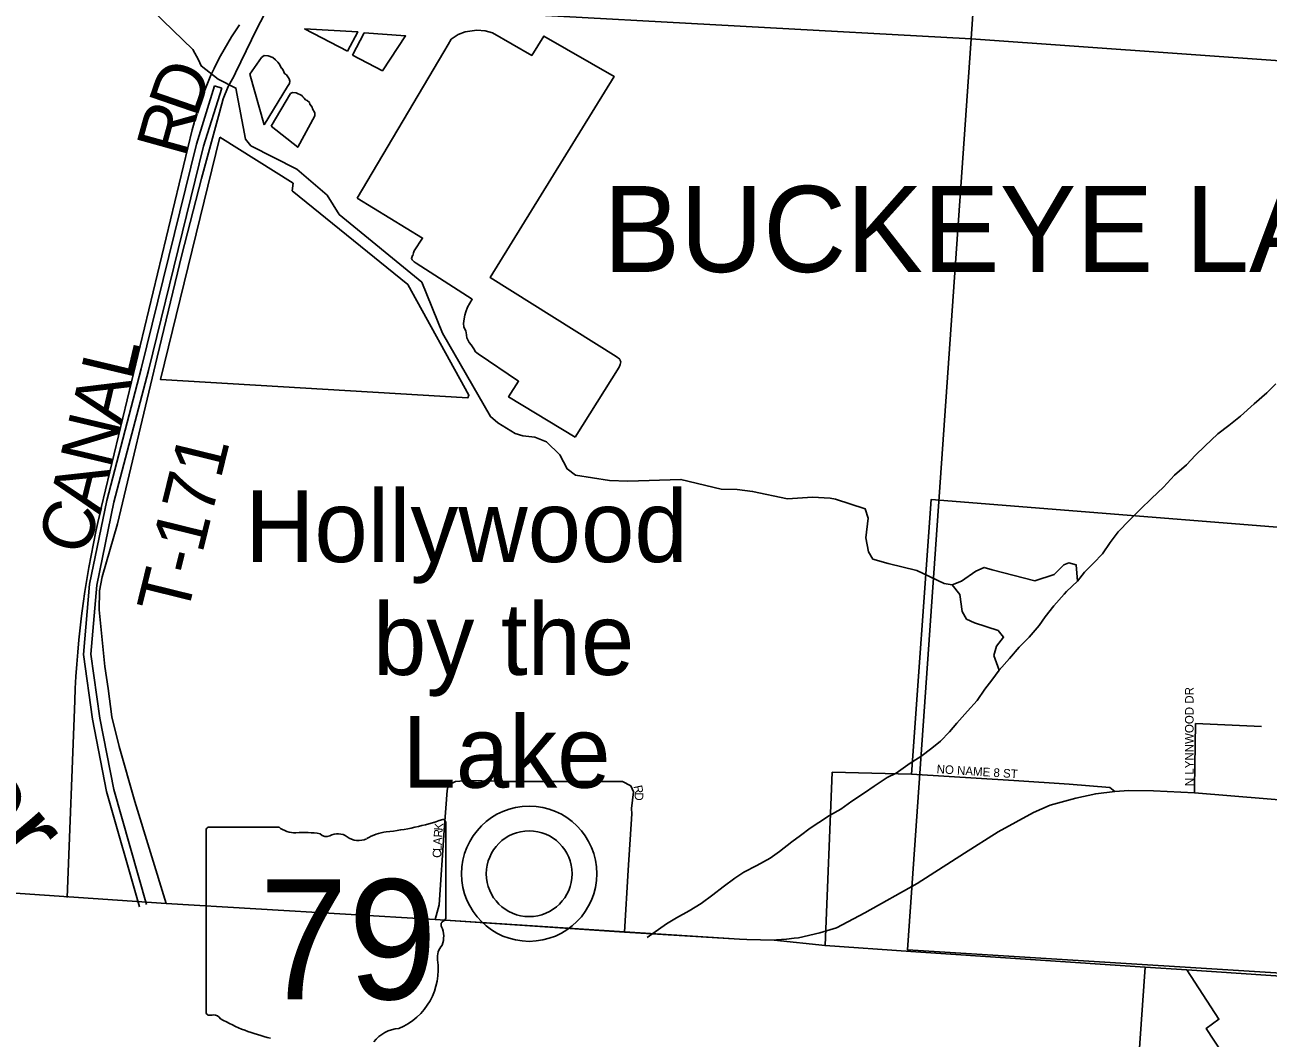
# Model space of a CAD drawing. Extents: x 0 to 40.4, y 0 to 22.
# Drawn here: x 4.97 to 6.339, y 14.615 to 15.73 of the extents above; entities that cross this region are included whole.
import ezdxf

# ---------------------------------------------------------------- set-up
doc = ezdxf.new("R2010")
doc.units = 0
for name, color, linetype in [('GM_X_Adjacent_County_Text', 7, 'Continuous'), ('GM_X_City_Street', 7, 'Continuous'), ('GM_X_City_Street_Text', 7, 'Continuous'), ('GM_X_Corporation', 7, 'Continuous'), ('GM_X_Corporation_Text', 7, 'Continuous'), ('GM_X_County', 7, 'Continuous'), ('GM_X_Major_River', 7, 'Continuous'), ('GM_X_Major_River_Text', 7, 'Continuous'), ('GM_X_Minor_Lake', 7, 'Continuous'), ('GM_X_Minor_River', 7, 'Continuous'), ('GM_X_Section', 7, 'Continuous'), ('GM_X_State_Route', 7, 'Continuous'), ('GM_X_State_Shield', 7, 'Continuous'), ('GM_X_Township_Road', 7, 'Continuous'), ('GM_X_Township_Road_Text', 7, 'Continuous'), ('GM_X_Township_Subdivision', 7, 'Continuous'), ('GM_X_Township_Subdivision_Text', 7, 'Continuous'), ('GM_X_Unincorporated', 7, 'Continuous'), ('GM_X_Unincorporated_Text', 7, 'Continuous'), ('SH_Data', 7, 'Continuous')]:
    doc.layers.add(name, color=color, linetype=linetype)

msp = doc.modelspace()

# ---------------------------------------------------------------- linework, layer by layer
at = {"layer": 'GM_X_City_Street'}
for points in [[(6.2578, 14.8849), (6.2579, 14.8912), (6.259, 14.961)], [(6.259, 14.961), (6.3317, 14.9578)], [(5.9465, 14.9054), (6.0591, 14.8982)], [(6.0591, 14.8982), (6.1198, 14.8943), (6.1646, 14.8906), (6.1702, 14.8863)]]:
    msp.add_lwpolyline(points, dxfattribs=at)
at = {"layer": 'GM_X_Corporation'}
for points in [[(6.1961, 14.5886), (6.2034, 14.693), (5.9456, 14.7103), (5.8513, 14.7168), (5.8591, 14.9075), (5.9465, 14.9054), (5.9681, 15.2076), (6.5188, 15.1635), (6.5553, 15.6693), (6.5616, 15.9075)], [(6.369, 14.682), (6.2494, 14.69), (6.2847, 14.6357), (6.2708, 14.6255), (6.2966, 14.5858)]]:
    msp.add_lwpolyline(points, dxfattribs=at)
at = {"layer": 'GM_X_County'}
msp.add_lwpolyline([(2.6, 14.9098), (3.7816, 14.849), (3.7947, 14.8444), (4.3781, 14.8049), (4.5187, 14.7962), (4.7718, 14.7855), (4.9113, 14.7777), (5.1259, 14.7632), (5.4221, 14.7453), (5.6303, 14.7317), (5.757, 14.7237), (5.765, 14.7235), (5.7951, 14.7228), (5.8513, 14.7168), (5.9456, 14.7103), (6.2034, 14.693), (6.2494, 14.69), (6.369, 14.682), (6.4224, 14.6785), (7.5441, 14.6124), (8.0846, 14.9692), (9.4, 14.8681)], dxfattribs=at)
at = {"layer": 'GM_X_Major_River'}
for points in [[(6.1144, 15.1035), (6.117, 15.1063), (6.1292, 15.1176), (6.1368, 15.1274), (6.1466, 15.1373), (6.1565, 15.1478), (6.1649, 15.1603), (6.174, 15.1721), (6.1865, 15.1849), (6.1983, 15.197), (6.2104, 15.2087), (6.2237, 15.2212), (6.2359, 15.2344), (6.2492, 15.2457), (6.259, 15.2563), (6.2693, 15.2661), (6.2837, 15.2797), (6.2955, 15.2888), (6.3084, 15.2993), (6.3236, 15.3126), (6.3376, 15.325), (6.3475, 15.3348)], [(5.6554, 14.7255), (5.6766, 14.7406), (5.6876, 14.7474), (5.7016, 14.755), (5.7149, 14.763), (5.7278, 14.7724), (5.7392, 14.7812), (5.7517, 14.791), (5.7619, 14.7975), (5.776, 14.8047), (5.7908, 14.813), (5.801, 14.8202), (5.8147, 14.8308), (5.8241, 14.8377), (5.8348, 14.846), (5.8443, 14.8521), (5.856, 14.86), (5.8685, 14.8668), (5.8807, 14.8756), (5.8947, 14.8847), (5.9053, 14.8923), (5.9194, 14.9017), (5.9296, 14.9063), (5.9448, 14.9173), (5.9565, 14.9249), (5.9687, 14.934), (5.9782, 14.9415), (5.988, 14.9518), (5.9964, 14.9616), (6.0081, 14.9745), (6.0188, 14.9863), (6.0271, 14.9988), (6.0347, 15.0087), (6.043, 15.0197), (6.0544, 15.0326), (6.065, 15.0451), (6.076, 15.0561), (6.0867, 15.069), (6.0935, 15.0785), (6.103, 15.0906), (6.1144, 15.1035)]]:
    msp.add_lwpolyline(points, dxfattribs=at)
at = {"layer": 'GM_X_Minor_Lake'}
for points in [[(5.278, 15.7255), (5.3254, 15.7007)], [(5.3254, 15.7007), (5.3368, 15.7222), (5.278, 15.7255)], [(5.3311, 15.6965), (5.364, 15.6793), (5.3895, 15.7175), (5.3438, 15.7211)], [(5.3438, 15.7211), (5.3311, 15.6965)], [(5.5762, 15.276), (5.6247, 15.3532), (5.6258, 15.3562), (5.6262, 15.3589), (5.6258, 15.3604), (5.6251, 15.3619), (5.6213, 15.365), (5.4827, 15.4516), (5.6189, 15.673), (5.5417, 15.7173), (5.5283, 15.6961), (5.4852, 15.7209), (5.4772, 15.7233), (5.4677, 15.724), (5.4552, 15.7222), (5.4472, 15.7192), (5.4396, 15.7139), (5.4362, 15.7082), (5.4316, 15.6999), (5.3362, 15.539)], [(5.2309, 15.6938), (5.2179, 15.6756), (5.2337, 15.6198)], [(5.2337, 15.6198), (5.2596, 15.6618), (5.2615, 15.6652), (5.2619, 15.6679), (5.2612, 15.6702), (5.2585, 15.6747), (5.2563, 15.6762), (5.2547, 15.68), (5.2532, 15.6819), (5.2529, 15.6819), (5.2502, 15.6869), (5.2487, 15.6888), (5.2461, 15.6911), (5.2434, 15.6937), (5.2381, 15.6957), (5.2336, 15.6961), (5.2309, 15.6938)], [(5.0965, 14.7595), (5.0601, 14.8864), (5.0448, 14.9657), (5.0348, 15.037), (5.0415, 15.1144), (5.0604, 15.2065), (5.0985, 15.3513), (5.1593, 15.5984), (5.1792, 15.6625)], [(5.1043, 14.7618), (5.0681, 14.8883), (5.0529, 14.967), (5.0431, 15.0373), (5.0496, 15.1132), (5.0684, 15.2047), (5.1064, 15.3493), (5.1671, 15.5962), (5.187, 15.6601)], [(5.1792, 15.6625), (5.187, 15.6601)], [(5.2895, 15.6298), (5.2895, 15.6329), (5.2868, 15.6374), (5.2865, 15.6393), (5.2842, 15.6424), (5.2835, 15.6443), (5.2812, 15.6466), (5.2793, 15.6473), (5.2778, 15.6492), (5.2763, 15.6504), (5.2751, 15.6519), (5.2691, 15.655), (5.2687, 15.655), (5.2649, 15.6554), (5.2626, 15.6542), (5.2416, 15.6183)], [(5.2416, 15.6183), (5.2708, 15.595), (5.2895, 15.6298)], [(5.1851, 15.6063), (5.1197, 15.3395), (5.458, 15.3194), (5.4591, 15.3223), (5.392, 15.444), (5.2645, 15.5472), (5.2657, 15.5556)], [(5.2657, 15.5556), (5.1851, 15.6063)], [(5.3362, 15.539), (5.4081, 15.4951), (5.399, 15.4811), (5.3982, 15.4788), (5.3975, 15.4758), (5.3971, 15.4758), (5.3959, 15.4728), (5.3967, 15.4713), (5.3986, 15.4694), (5.3989, 15.469), (5.4012, 15.4674), (5.4629, 15.4278), (5.4576, 15.4191), (5.4557, 15.4141), (5.4545, 15.4103), (5.4541, 15.4062), (5.4533, 15.4012), (5.4537, 15.3974), (5.4556, 15.3929), (5.456, 15.3914), (5.4567, 15.3853), (5.4593, 15.3804), (5.4616, 15.3777), (5.4646, 15.3731), (5.4665, 15.3701), (5.4695, 15.3678), (5.5138, 15.3377), (5.5028, 15.3203), (5.5762, 15.276)]]:
    msp.add_lwpolyline(points, dxfattribs=at)
at = {"layer": 'GM_X_Minor_River'}
for points in [[(6.1292, 15.1176), (6.1277, 15.1355), (6.1197, 15.1378), (6.114, 15.1356), (6.1034, 15.125), (6.0821, 15.1182), (6.0351, 15.1302), (6.0264, 15.1328), (6.0173, 15.1287), (6.0013, 15.1178), (5.9911, 15.1136), (5.9823, 15.1152), (5.9524, 15.1293), (5.9206, 15.137), (5.9039, 15.142), (5.899, 15.15), (5.896, 15.1652), (5.8987, 15.1868), (5.8954, 15.1971), (5.8628, 15.2078), (5.8567, 15.209), (5.8374, 15.2102), (5.8097, 15.2084), (5.7714, 15.2165), (5.7543, 15.2184), (5.7369, 15.2189), (5.6925, 15.2297), (5.6341, 15.2276), (5.614, 15.2284), (5.5765, 15.2343), (5.5674, 15.2411), (5.5591, 15.2567), (5.5447, 15.2708), (5.5318, 15.2761), (5.5186, 15.2777), (5.5102, 15.28), (5.4909, 15.2918), (5.483, 15.2987), (5.4302, 15.3907), (5.4072, 15.4466), (5.3164, 15.5212), (5.3032, 15.5422), (5.2699, 15.5711), (5.2192, 15.5967), (5.2131, 15.6039), (5.2027, 15.6601), (5.183, 15.6701), (5.1645, 15.6845), (5.1615, 15.6914), (5.1551, 15.7028), (4.969, 15.8829)], [(6.043, 15.0197), (6.0371, 15.0357), (6.0398, 15.0463), (6.0478, 15.0561), (6.0417, 15.0634), (6.0156, 15.0718), (6.0069, 15.076), (6.002, 15.0844), (5.9997, 15.103), (5.9911, 15.1136)]]:
    msp.add_lwpolyline(points, dxfattribs=at)
at = {"layer": 'GM_X_Section'}
for points in [[(6.0805, 16.728), (6.012, 15.7142), (5.5033, 15.7422), (5.57, 16.7542)], [(6.0805, 16.728), (6.3929, 16.7053), (6.6625, 16.6858), (6.5945, 15.6728), (6.012, 15.7142)], [(6.012, 15.7142), (6.5945, 15.6728), (6.5001, 14.6771), (5.9421, 14.7119)]]:
    msp.add_lwpolyline(points, close=True, dxfattribs=at)
at = {"layer": 'GM_X_State_Route'}
for points in [[(5.8173, 14.7248), (5.822, 14.7253), (5.8456, 14.7308), (5.8638, 14.7362), (5.895, 14.7527), (5.9526, 14.7852), (6.0047, 14.8184), (6.0416, 14.8418), (6.0806, 14.8632), (6.099, 14.8711), (6.1272, 14.8789), (6.1491, 14.8838), (6.1702, 14.8863), (6.1857, 14.8875), (6.2126, 14.8871), (6.2578, 14.8849), (6.3777, 14.875), (6.4338, 14.8704), (6.4868, 14.8662)], [(3.7816, 14.849), (3.7947, 14.8444), (4.3781, 14.8049), (4.5187, 14.7962), (4.7718, 14.7855), (4.9113, 14.7777), (5.1259, 14.7632)], [(5.1259, 14.7632), (5.4221, 14.7453), (5.6303, 14.7316), (5.757, 14.7237), (5.765, 14.7235), (5.7951, 14.7228), (5.7977, 14.723)], [(5.7977, 14.723), (5.8087, 14.7239), (5.8173, 14.7248)]]:
    msp.add_lwpolyline(points, dxfattribs=at)
at = {"layer": 'GM_X_State_Shield'}
for p, q in [((5.4336, 14.7474), (5.4336, 14.8521)), ((5.17, 14.8437), (5.17, 14.6436)), ((5.2498, 14.8471), (5.1726, 14.8471)), ((5.4336, 14.7474), (5.4336, 14.7474))]:
    msp.add_line(p, q, dxfattribs=at)
for centre, radius, start, end in [((5.3397, 15.12), 0.2796, 275.8445, 288.9065), ((5.4307, 14.8525), 0.00294, 351.8621, 97.738), ((5.173, 14.8441), 0.00305, 98.1301, 188.1301), ((5.2682, 14.8704), 0.0296, 231.6195, 271.1119), ((5.278, 14.7348), 0.1064, 80.4867, 94.9883), ((5.3021, 14.8451), 0.00855, 219.7921, 297.1024), ((5.3147, 14.822), 0.0178, 54.4667, 119.1411), ((5.3376, 14.8537), 0.0214, 233.8562, 294.8282), ((5.3754, 14.786), 0.0563, 97.3462, 120.7689), ((5.433, 14.7397), 0.00454, 107.944, 210.337), ((5.4305, 14.747), 0.00314, 289.6038, 7.7341), ((5.4041, 14.7265), 0.0273, 340.033, 23.6496), ((5.4442, 14.7036), 0.0198, 136.8065, 186.9296), ((5.3554, 14.6903), 0.0699, 292.3089, 8.9858), ((5.173, 14.6431), 0.00308, 171.9584, 258.3066), ((5.1735, 14.6636), 0.0235, 267.339, 280.6039), ((5.1783, 14.632), 0.00848, 29.7484, 93.2717), ((5.2854, 14.8118), 0.2019, 240.4129, 257.1985), ((5.3849, 14.5874), 0.0383, 94.4031, 142.5768)]:
    msp.add_arc(centre, radius, start, end, dxfattribs=at)
at = {"layer": 'GM_X_Township_Road'}
for points in [[(5.2022, 15.6769), (5.2257, 15.7255), (5.2467, 15.7656), (5.2646, 15.7968), (5.2981, 15.843), (5.3281, 15.8846), (5.3786, 15.9538), (5.3927, 15.9705), (5.4131, 15.9925), (5.4141, 15.9936)], [(5.1259, 14.7632), (5.0915, 14.8753), (5.0743, 14.9356), (5.066, 14.9685), (5.0619, 14.9997), (5.0583, 15.0237), (5.0523, 15.0863), (5.0526, 15.1071), (5.0556, 15.1225), (5.0724, 15.1806), (5.1161, 15.364), (5.1432, 15.4766), (5.1648, 15.5608), (5.1845, 15.6332), (5.1888, 15.6484), (5.1942, 15.662), (5.1975, 15.6679), (5.2003, 15.673), (5.2022, 15.6769)]]:
    msp.add_lwpolyline(points, dxfattribs=at)
at = {"layer": 'GM_X_Township_Subdivision'}
msp.add_lwpolyline([(5.4221, 14.7453), (5.4265, 14.7616), (5.4318, 14.8438), (5.4351, 14.8872), (5.4358, 14.8909), (5.4394, 14.8948), (5.4445, 14.8973), (5.4588, 14.8983), (5.503, 14.8973), (5.5646, 14.8973), (5.6281, 14.8973), (5.6373, 14.8925), (5.6402, 14.8859), (5.6381, 14.8675), (5.6384, 14.8616), (5.6345, 14.7996), (5.6303, 14.7316)], dxfattribs=at)
at = {"layer": 'GM_X_Unincorporated'}
for radius in [0.0744, 0.0472]:
    msp.add_circle((5.5255, 14.7958), radius, dxfattribs=at)
at = {"layer": 'SH_Data'}
for p, q in [((5.1546, 15.6143), (5.0545, 15.1985)), ((5.0252, 14.986), (5.0169, 14.7695))]:
    msp.add_line(p, q, dxfattribs=at)
for centre, radius, start, end in [((5.483, 15.5352), 0.3378, 144.8523, 166.4701), ((6.1096, 14.9446), 1.0852, 166.4701, 177.8139)]:
    msp.add_arc(centre, radius, start, end, dxfattribs=at)

# ---------------------------------------------------------------- texts
at = {"layer": 'GM_X_Adjacent_County_Text'}
msp.add_text('FAIRFIELD COUNTY', height=0.189394, rotation=356.4928, dxfattribs=at).set_placement((3.8944, 14.4406))
at = {"layer": 'GM_X_City_Street_Text'}
for s, rotation, p in [('N LYNNWOOD DR', 90, (6.2569, 14.8921)), ('NO NAME 8 ST', 356.3857, (5.9738, 14.9064))]:
    msp.add_text(s, height=0.00947, rotation=rotation, dxfattribs=at).set_placement(p)
at = {"layer": 'GM_X_Corporation_Text'}
msp.add_text('BUCKEYE LAKE', height=0.094697, rotation=0, dxfattribs=at).set_placement((5.6071, 15.4578))
at = {"layer": 'GM_X_Major_River_Text'}
msp.add_text('River', height=0.09471, rotation=309.9946, dxfattribs=at).set_placement((4.7619, 15.0179))
at = {"layer": 'GM_X_State_Shield'}
msp.add_text('79', height=0.13184, dxfattribs=at).set_placement((5.2281, 14.6577))
at = {"layer": 'GM_X_Township_Road_Text'}
for s, height, rotation, p in [('D', 0.0568, 70.9833, (5.1593, 15.6262)), ('R', 0.0568, 74.4519, (5.1471, 15.5822)), ('L', 0.0568, 76.6497, (5.0871, 15.3375)), ('A', 0.0568, 76.6493, (5.0756, 15.2889)), ('N', 0.0568, 76.6481, (5.064, 15.2402)), ('T-171', 0.05682, 76.1527, (5.1484, 15.0772)), ('A', 0.0568, 76.0939, (5.0519, 15.1911)), ('C', 0.0568, 73.7785, (5.0382, 15.1439))]:
    msp.add_text(s, height=height, rotation=rotation, dxfattribs=at).set_placement(p)
at = {"layer": 'GM_X_Township_Subdivision_Text'}
for s, rotation, p in [('R', 281.8862, (5.6403, 14.8921)), ('D', 269.8907, (5.6417, 14.8853)), ('K', 84.9223, (5.4302, 14.8429)), ('A', 86.8855, (5.4293, 14.8272)), ('R', 86.5979, (5.4298, 14.8355)), ('C', 86.8902, (5.4285, 14.813)), ('L', 86.8838, (5.4289, 14.8205))]:
    msp.add_text(s, height=0.00947, rotation=rotation, dxfattribs=at).set_placement(p)
at = {"layer": 'GM_X_Unincorporated_Text'}
for s, p in [('Hollywood', (5.2128, 15.1387)), ('by the', (5.3536, 15.0145)), ('Lake', (5.3861, 14.8904))]:
    msp.add_text(s, height=0.07898, rotation=0, dxfattribs=at).set_placement(p)

doc.saveas('drawing.dxf')
